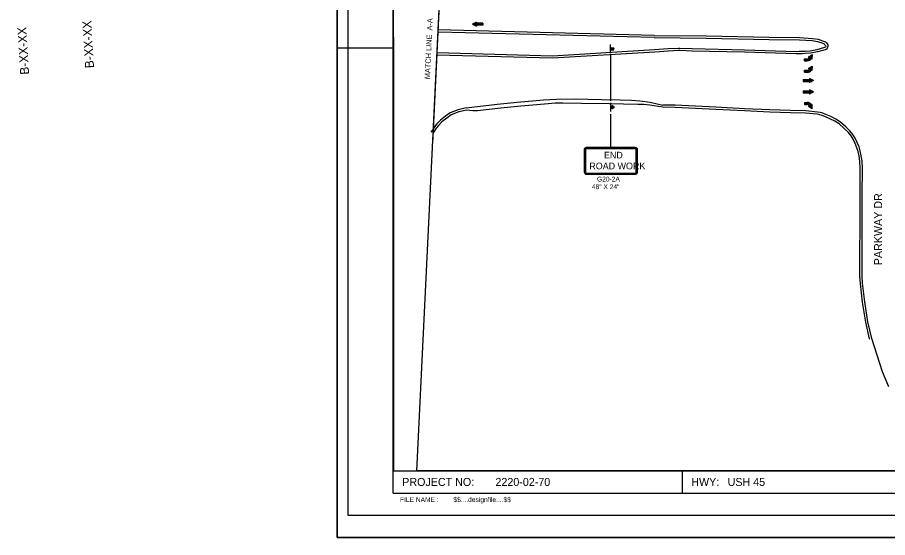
# Model space of a CAD drawing. Extents: x 360065 to 362124, y 174333 to 175433.
# Drawn here: x 360065 to 361043, y 174333 to 174917 of the extents above; entities that cross this region are included whole.
import ezdxf

# ---------------------------------------------------------------- set-up
doc = ezdxf.new("R2010")
doc.units = 0
for name, color, linetype in [('Default', 7, 'Continuous'), ('P_ALI_100_PIData', 7, 'Continuous'), ('P_ALI_100_Sta', 7, 'Continuous'), ('P_ALI_20', 7, 'Continuous'), ('P_ALI_200_Equation', 7, 'Continuous'), ('P_ALI_20_Equation', 7, 'Continuous'), ('P_ALI_20_Sta', 7, 'Continuous'), ('P_ALI_20_Tic', 7, 'Continuous'), ('P_ALI_500_PIData', 7, 'Continuous'), ('P_ALI_500_Sta', 7, 'Continuous'), ('P_ALI_50_Equation', 7, 'Continuous'), ('P_ALI_50_Tic', 7, 'Continuous')]:
    doc.layers.add(name, color=color, linetype=linetype)

msp = doc.modelspace()

# ---------------------------------------------------------------- linework, layer by layer
for p, q in [((360487.36, 174382.95), (360487.36, 175382.95)), ((360424.11, 174857.95), (360424.11, 174907.95)), ((360424.11, 174882.95), (360487.36, 174882.95)), ((360524.86, 174882.95), (360524.86, 174882.95)), ((360487.36, 174407.95), (362062.36, 174407.95)), ((360812.36, 174382.95), (360812.36, 174407.95)), ((360424.11, 174332.95), (360424.11, 174382.95)), ((360487.36, 174382.95), (362062.36, 174382.95)), ((360424.11, 174332.95), (360474.11, 174332.95))]:
    msp.add_line(p, q)
at = {"layer": 'Default'}
msp.add_lwpolyline([(362007.43, 175382.95), (362007.43, 174984.32), (362007.43, 174408.5), (360513.97, 174407.95), (360560.89, 175382.95)], close=True, dxfattribs=at)
msp.add_lwpolyline([(362007.43, 175382.95), (362007.43, 174984.32), (362007.43, 174408.5), (360513.97, 174407.95), (360560.89, 175382.95)], close=True, dxfattribs=at)
msp.add_lwpolyline([(362007.43, 175382.95), (362007.43, 174984.32), (362007.43, 174408.5), (360513.97, 174407.95), (360560.89, 175382.95)], close=True, dxfattribs=at)
at = {"layer": 'P_ALI_100_PIData'}
for p, q in [((360731.85, 174823.4), (360731.85, 174875.77)), ((360731.85, 174771.02), (360731.85, 174808.7))]:
    msp.add_line(p, q, dxfattribs=at)
at = {"layer": 'P_ALI_100_Sta'}
for p, q in [((360731.68, 174876.93), (360731.68, 174886.93)), ((360731.92, 174811.47), (360731.92, 174821.47))]:
    msp.add_line(p, q, dxfattribs=at)
for centre, radius in [((360733.43, 174881.9), 1.75), ((360733.43, 174881.9), 1), ((360733.43, 174881.9), 0.25), ((360733.67, 174816.45), 1.75), ((360733.67, 174816.45), 1), ((360733.67, 174816.45), 0.25)]:
    msp.add_circle(centre, radius, dxfattribs=at)
at = {"layer": 'P_ALI_20'}
for points in [[(360424.11, 174332.95), (362124.11, 174332.95), (362124.11, 175432.95), (360424.11, 175432.95)], [(360436.11, 174357.95), (362091.11, 174357.95), (362091.11, 175407.95), (360436.11, 175407.95)]]:
    msp.add_lwpolyline(points, close=True, dxfattribs=at)
at = {"layer": 'P_ALI_200_Equation'}
msp.add_lwpolyline([(360424.11, 175432.95), (362124.11, 175432.95), (362124.11, 174332.95), (360424.11, 174332.95), (360424.11, 175432.95)], dxfattribs=at)
at = {"layer": 'P_ALI_20_Equation'}
for p, q in [((360780.76, 174894.62), (360537.68, 174900.65)), ((360780.69, 174897.12), (360537.8, 174903.15)), ((360666.33, 174873.89), (360536.56, 174877.36)), ((360781.12, 174880.88), (360666.33, 174873.89)), ((360781.18, 174878.38), (360666.4, 174871.39)), ((360666.4, 174871.39), (360536.44, 174874.86))]:
    msp.add_line(p, q, dxfattribs=at)
for points in [[(360780.69, 174897.12), (360839.17, 174896.49), (360909.82, 174895.01), (360944, 174894.71), (360958.61, 174893.76), (360965.02, 174892.78), (360970.02, 174891.13), (360971.95, 174890.4), (360973.26, 174889.69), (360974.21, 174888.56), (360975.72, 174886.57), (360976, 174884.53), (360975.3, 174882.77), (360974.26, 174881.73), (360973.05, 174881.01), (360964.1, 174878.49), (360956.38, 174877.04), (360950.4, 174876.58), (360947.03, 174876.33), (360943.74, 174876.31), (360940.36, 174876.25), (360882.07, 174878.08), (360823.35, 174879.53), (360809.57, 174880.03), (360807.97, 174880.01), (360796.66, 174879.35), (360781.18, 174878.38)], [(360780.76, 174894.62), (360839.13, 174893.99), (360909.78, 174892.51), (360943.91, 174892.21), (360958.34, 174891.27), (360964.43, 174890.34), (360969.19, 174888.77), (360970.91, 174888.13), (360971.65, 174887.72), (360972.26, 174887), (360973.34, 174885.58), (360973.44, 174884.84), (360973.17, 174884.18), (360972.72, 174883.72), (360972.06, 174883.33), (360963.53, 174880.92), (360956.05, 174879.52), (360950.21, 174879.07), (360946.93, 174878.83), (360943.71, 174878.81), (360940.38, 174878.76), (360882.14, 174880.58), (360823.43, 174882.03), (360809.6, 174882.53), (360807.89, 174882.51), (360796.51, 174881.85), (360781.12, 174880.88)], [(360569.28, 174815.65), (360604.2, 174819.88), (360626.66, 174821.95), (360647.99, 174824.08), (360656.11, 174824.87), (360670.8, 174825.52), (360690.7, 174825.8), (360721.34, 174825.22), (360742.36, 174824.74), (360755.04, 174824.23), (360764.64, 174823.52), (360776.1, 174822.24), (360790.46, 174818.83)], [(360790.42, 174816.43), (360775.8, 174818.7), (360768.83, 174819.35), (360762.16, 174819.6), (360729.98, 174820.28), (360699.04, 174820.58), (360677.84, 174821.07), (360669.42, 174820.88), (360661.38, 174820.33), (360648.56, 174819.19), (360630.89, 174817.51), (360608.24, 174815.2), (360591.81, 174813.35), (360581.82, 174812.41), (360576.71, 174812.23), (360569.85, 174813.22)], [(361044.41, 174502.29), (361037.33, 174519.21), (361025.27, 174556.71), (361020.98, 174575.49), (361017.46, 174597.71), (361014.98, 174618.57), (361014.42, 174626.84), (361014.36, 174649.87), (361014.63, 174685.16), (361014.58, 174717.95), (361014.86, 174747.48), (361014.29, 174756.11), (361013.51, 174761.85), (361012.35, 174767.25), (361010.95, 174771.72), (361008.89, 174776.74), (361006.64, 174781.6), (361004.01, 174785.58), (361000.57, 174789.98), (360996, 174794.24), (360990.16, 174799.58), (360984.83, 174803.08), (360979.13, 174805.8), (360973.49, 174808.39), (360970.3, 174809.58), (360967.36, 174810.31), (360964.26, 174811.02), (360950.96, 174812.27), (360933.91, 174812.57), (360910.65, 174813.47), (360882.21, 174814.68), (360849.9, 174816.28), (360804.27, 174818.57), (360790.46, 174818.83)], [(360569.28, 174815.65), (360560.12, 174813.49), (360551.38, 174809.99), (360545.9, 174806.27), (360540.21, 174801.67), (360536.41, 174797.56), (360533.67, 174794.29), (360530.94, 174790.24), (360529.68, 174788.22)], [(360569.85, 174813.22), (360560.87, 174811.1), (360552.56, 174807.77), (360547.39, 174804.26), (360541.92, 174799.84), (360538.29, 174795.91), (360535.67, 174792.79), (360533.04, 174788.88), (360531.8, 174786.9)], [(361022.96, 174555.72), (361022.85, 174556.04), (361018.52, 174575.02), (361014.98, 174597.36), (361012.49, 174618.34), (361011.92, 174626.76), (361011.86, 174649.88), (361012.13, 174685.17), (361012.08, 174717.96), (361012.36, 174747.4), (361011.8, 174755.86), (361011.04, 174761.42), (361009.93, 174766.61), (361008.6, 174770.87), (361006.6, 174775.74), (361004.46, 174780.37), (361001.98, 174784.11), (360998.72, 174788.28), (360994.3, 174792.4), (360988.62, 174797.6), (360983.6, 174800.89), (360978.07, 174803.53), (360972.53, 174806.08), (360969.56, 174807.18), (360966.78, 174807.88), (360963.86, 174808.54), (360950.82, 174809.78), (360933.84, 174810.07), (360910.55, 174810.98), (360882.1, 174812.18), (360849.78, 174813.79), (360804.18, 174816.07), (360790.41, 174816.33)]]:
    msp.add_lwpolyline(points, dxfattribs=at)
at = {"layer": 'P_ALI_20_Sta'}
msp.add_lwpolyline([(360424.11, 175432.95), (362124.11, 175432.95), (362124.11, 174332.95), (360424.11, 174332.95)], close=True, dxfattribs=at)
at = {"layer": 'P_ALI_20_Tic'}
msp.add_line((360531.68, 174775.82), (360541.63, 174982.64), dxfattribs=at)
at = {"layer": 'P_ALI_500_PIData'}
for p, q in [((360576.29, 174909.72), (360580.69, 174911.93)), ((360576.29, 174909.72), (360580.69, 174907.43)), ((360587.81, 174909.91), (360576.67, 174909.91)), ((360587.81, 174909.46), (360576.79, 174909.46)), ((360587.81, 174910.36), (360577.56, 174910.36)), ((360587.81, 174909.01), (360577.66, 174909.01)), ((360580.66, 174910.81), (360578.46, 174910.81)), ((360580.66, 174908.56), (360578.52, 174908.56)), ((360580.66, 174911.26), (360579.35, 174911.26)), ((360580.66, 174908.11), (360579.39, 174908.11)), ((360580.66, 174911.71), (360580.24, 174911.71)), ((360580.66, 174907.66), (360580.25, 174907.66)), ((360580.69, 174911.93), (360580.69, 174907.43)), ((360587.81, 174910.81), (360580.69, 174910.81)), ((360587.81, 174908.56), (360580.69, 174908.56)), ((360587.81, 174910.81), (360587.81, 174908.56)), ((360587.81, 174909.68), (360587.81, 174909.68)), ((360949.57, 174868.59), (360949.57, 174870.84)), ((360949.57, 174870.84), (360952.66, 174870.84)), ((360949.57, 174870.39), (360952.66, 174870.39)), ((360949.57, 174869.94), (360952.66, 174869.94)), ((360949.57, 174869.72), (360949.57, 174869.72)), ((360949.57, 174869.49), (360952.66, 174869.49)), ((360949.57, 174869.04), (360952.66, 174869.04)), ((360949.57, 174868.59), (360952.66, 174868.59)), ((360954.1, 174872.79), (360958.24, 174875.47)), ((360955.07, 174872.23), (360954.1, 174872.79)), ((360954.29, 174872.68), (360954.51, 174873.06)), ((360954.68, 174872.46), (360955.34, 174873.6)), ((360955.07, 174872.23), (360956.17, 174874.13)), ((360955.46, 174872.01), (360957, 174874.67)), ((360955.85, 174871.78), (360957.83, 174875.21)), ((360956.24, 174871.56), (360958.22, 174874.98)), ((360956.63, 174871.33), (360958.16, 174873.99)), ((360957.01, 174871.1), (360958.11, 174873)), ((360957.99, 174870.54), (360957.01, 174871.1)), ((360957.4, 174870.87), (360958.06, 174872.02)), ((360957.79, 174870.65), (360958.01, 174871.03)), ((360958.24, 174875.47), (360957.99, 174870.54)), ((360949.57, 174855.59), (360949.57, 174857.84)), ((360949.57, 174857.84), (360952.66, 174857.84)), ((360954.1, 174859.79), (360958.24, 174862.47)), ((360955.07, 174859.23), (360954.1, 174859.79)), ((360954.29, 174859.68), (360954.51, 174860.06)), ((360954.68, 174859.46), (360955.34, 174860.6)), ((360955.07, 174859.23), (360956.17, 174861.13)), ((360955.46, 174859.01), (360957, 174861.67)), ((360955.85, 174858.78), (360957.83, 174862.21)), ((360956.24, 174858.56), (360958.22, 174861.98)), ((360956.63, 174858.33), (360958.16, 174860.99)), ((360957.01, 174858.1), (360958.11, 174860)), ((360957.99, 174857.54), (360957.01, 174858.1)), ((360957.4, 174857.87), (360958.06, 174859.02)), ((360957.79, 174857.65), (360958.01, 174858.03)), ((360958.24, 174862.47), (360957.99, 174857.54)), ((360948.07, 174847.67), (360948.07, 174845.42)), ((360948.07, 174847.67), (360955.19, 174847.67)), ((360949.57, 174857.39), (360952.66, 174857.39)), ((360949.57, 174856.94), (360952.66, 174856.94)), ((360949.57, 174856.72), (360949.57, 174856.72)), ((360949.57, 174856.49), (360952.66, 174856.49)), ((360949.57, 174856.04), (360952.66, 174856.04)), ((360949.57, 174855.59), (360952.66, 174855.59)), ((360959.59, 174846.58), (360955.2, 174848.79)), ((360955.2, 174848.79), (360955.2, 174844.29)), ((360955.22, 174848.57), (360955.64, 174848.57)), ((360955.22, 174848.12), (360956.53, 174848.12)), ((360955.22, 174847.67), (360957.43, 174847.67)), ((360948.07, 174847.22), (360958.32, 174847.22)), ((360948.07, 174846.77), (360959.21, 174846.77)), ((360948.07, 174846.54), (360948.07, 174846.54)), ((360948.07, 174846.32), (360959.09, 174846.32)), ((360948.07, 174845.87), (360958.22, 174845.87)), ((360948.07, 174845.42), (360955.19, 174845.42)), ((360959.59, 174846.58), (360955.2, 174844.29)), ((360955.22, 174845.42), (360957.36, 174845.42)), ((360955.22, 174844.97), (360956.49, 174844.97)), ((360955.22, 174844.52), (360955.63, 174844.52)), ((360948.07, 174834.67), (360948.07, 174832.42)), ((360948.07, 174834.67), (360955.19, 174834.67)), ((360948.07, 174834.22), (360958.32, 174834.22)), ((360948.07, 174833.77), (360959.21, 174833.77)), ((360948.07, 174833.54), (360948.07, 174833.54)), ((360948.07, 174833.32), (360959.09, 174833.32)), ((360948.07, 174832.87), (360958.22, 174832.87)), ((360948.07, 174832.42), (360955.19, 174832.42)), ((360959.59, 174833.58), (360955.2, 174835.79)), ((360955.2, 174835.79), (360955.2, 174831.29)), ((360959.59, 174833.58), (360955.2, 174831.29)), ((360955.22, 174835.57), (360955.64, 174835.57)), ((360955.22, 174835.12), (360956.53, 174835.12)), ((360955.22, 174834.67), (360957.43, 174834.67)), ((360955.22, 174832.42), (360957.36, 174832.42)), ((360955.22, 174831.97), (360956.49, 174831.97)), ((360955.22, 174831.52), (360955.63, 174831.52)), ((360949.57, 174821.81), (360949.57, 174819.56)), ((360949.57, 174821.81), (360952.66, 174821.81)), ((360949.57, 174821.36), (360952.66, 174821.36)), ((360949.57, 174820.91), (360952.66, 174820.91)), ((360949.57, 174820.69), (360949.57, 174820.69)), ((360949.57, 174820.46), (360952.66, 174820.46)), ((360949.57, 174820.01), (360952.66, 174820.01)), ((360949.57, 174819.56), (360952.66, 174819.56)), ((360955.46, 174818.39), (360957, 174815.73)), ((360955.85, 174818.62), (360957.83, 174815.19)), ((360956.24, 174818.84), (360958.22, 174815.42)), ((360956.63, 174819.07), (360958.16, 174816.41)), ((360957.99, 174819.86), (360957.01, 174819.3)), ((360957.01, 174819.3), (360958.11, 174817.4)), ((360957.4, 174819.53), (360958.06, 174818.38)), ((360957.79, 174819.75), (360958.01, 174819.37)), ((360958.24, 174814.93), (360957.99, 174819.86)), ((360955.07, 174818.17), (360954.1, 174817.61)), ((360954.1, 174817.61), (360958.24, 174814.93)), ((360954.29, 174817.72), (360954.51, 174817.34)), ((360954.68, 174817.94), (360955.34, 174816.8)), ((360955.07, 174818.17), (360956.17, 174816.27))]:
    msp.add_line(p, q, dxfattribs=at)
for centre, radius, start, end in [((360952.66, 174873.62), 2.78, 270, 330.00328), ((360952.66, 174873.62), 3.23, 270, 330.00328), ((360952.66, 174873.62), 3.68, 270, 330.00328), ((360952.66, 174873.62), 4.13, 270, 330.00328), ((360952.66, 174873.62), 4.58, 270, 330.00328), ((360952.66, 174873.62), 5.03, 270, 330.00328), ((360952.66, 174860.62), 2.78, 270, 330.00328), ((360952.66, 174860.62), 3.23, 270, 330.00328), ((360952.66, 174860.62), 3.68, 270, 330.00328), ((360952.66, 174860.62), 4.13, 270, 330.00328), ((360952.66, 174860.62), 4.58, 270, 330.00328), ((360952.66, 174860.62), 5.03, 270, 330.00328), ((360952.66, 174816.78), 5.03, 29.99672, 90), ((360952.66, 174816.78), 4.58, 29.99672, 90), ((360952.66, 174816.78), 4.13, 29.99672, 90), ((360952.66, 174816.78), 3.68, 29.99672, 90), ((360952.66, 174816.78), 3.23, 29.99672, 90), ((360952.66, 174816.78), 2.78, 29.99672, 90)]:
    msp.add_arc(centre, radius, start, end, dxfattribs=at)
at = {"layer": 'P_ALI_500_Sta'}
for p, q in [((360759.42, 174771.02), (360704.27, 174771.02)), ((360759.42, 174770.39), (360704.42, 174770.39)), ((360759.42, 174769.61), (360704.42, 174769.61)), ((360701.92, 174768.52), (360701.92, 174743.52)), ((360702.55, 174768.52), (360702.55, 174743.52)), ((360703.33, 174768.52), (360703.33, 174743.52)), ((360760.52, 174743.52), (360760.52, 174768.52)), ((360761.3, 174743.52), (360761.3, 174768.52)), ((360761.92, 174743.52), (360761.92, 174768.52)), ((360704.42, 174742.42), (360759.42, 174742.42)), ((360704.42, 174741.64), (360759.42, 174741.64)), ((360704.42, 174741.02), (360759.42, 174741.02))]:
    msp.add_line(p, q, dxfattribs=at)
for centre, radius, start, end in [((360704.42, 174768.52), 2.5, 93.57633, 180), ((360704.42, 174768.52), 1.88, 90, 180), ((360704.42, 174768.52), 1.1, 90, 180), ((360759.42, 174768.52), 2.5, 0, 90), ((360759.42, 174768.52), 1.88, 0, 90), ((360759.42, 174768.52), 1.09, 0, 90), ((360704.43, 174743.52), 2.5, 180, 270), ((360704.42, 174743.52), 1.88, 180, 270), ((360704.44, 174743.52), 1.1, 180, 270), ((360759.42, 174743.52), 1.88, 270, 360), ((360759.42, 174743.52), 1.1, 270, 360), ((360759.42, 174743.52), 2.5, 270, 360)]:
    msp.add_arc(centre, radius, start, end, dxfattribs=at)
at = {"layer": 'P_ALI_50_Tic'}
msp.add_lwpolyline([(362062.02, 175383.5), (360487.36, 175382.95), (360487.7, 174407.95)], dxfattribs=at)

# ---------------------------------------------------------------- texts
for s, height, rotation, p in [('PROJECT NO:', 9, 360, (360497.36, 174390.95)), (' 2220-02-70', 9, 360, (360598.86, 174390.95)), ('HWY:', 9, 360, (360822.36, 174390.95)), (' USH 45', 9, 360, (360859.86, 174390.95)), ('FILE NAME :', 5.4, 360, (360494.86, 174372.95)), ('$$....designfile....$$', 5.4, 359.99998, (360554.86, 174372.95))]:
    msp.add_text(s, height=height, rotation=rotation).set_placement(p)
at = {"layer": 'P_ALI_100_PIData'}
for p in [(360077.93, 174853.27), (360150.91, 174860.52)]:
    msp.add_text('B-XX-XX', height=10, rotation=93.49764, dxfattribs=at).set_placement(p)
at = {"layer": 'P_ALI_500_Sta'}
for s, height, p in [('END', 7.5, (360724.17, 174758.79)), ('ROAD WORK', 7.5, (360707.72, 174746.63)), ('G20-2A', 5.4, (360716.36, 174732.94)), ('48" X 24"', 5.4, (360710.57, 174724.37))]:
    msp.add_text(s, height=height, dxfattribs=at).set_placement(p)
at = {"layer": 'P_ALI_50_Equation'}
for s, height, rotation, p in [('MATCH LINE  A-A', 6, 87.27072, (360528.48, 174847.77)), ('PARKWAY DR', 9, 90, (361036.88, 174638.87))]:
    msp.add_text(s, height=height, rotation=rotation, dxfattribs=at).set_placement(p)

doc.saveas('drawing.dxf')
